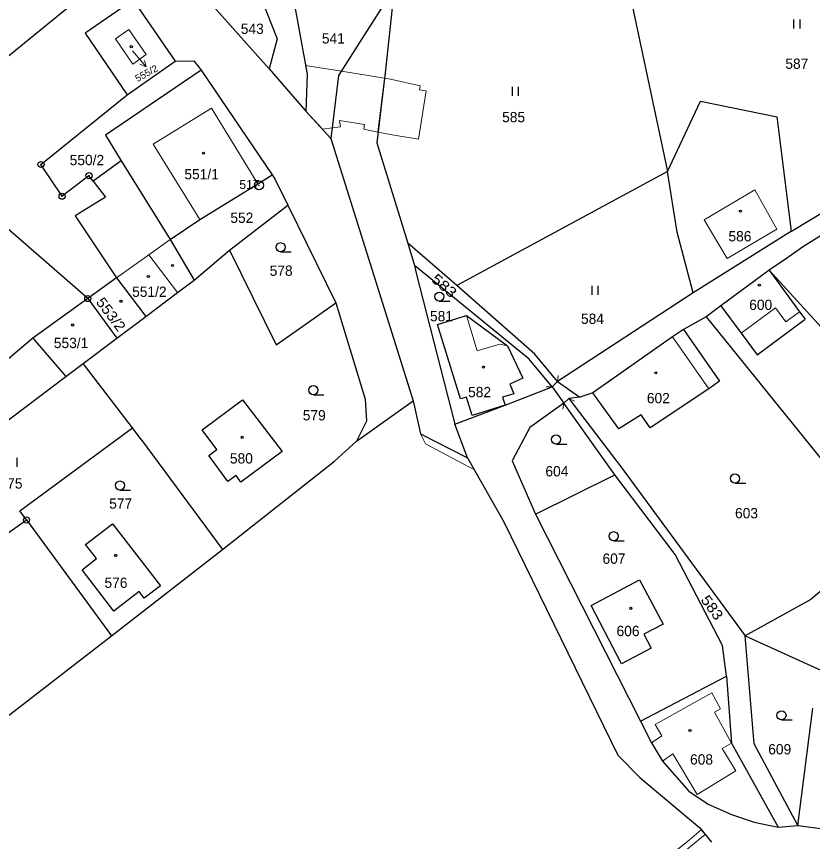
# Model space of a CAD drawing. Extents: x -727701 to -724405, y -960481 to -957284.
# Drawn here: x -726659.3 to -726527.9, y -958649.2 to -958512.9 of the extents above; entities that cross this region are included whole.
import ezdxf
from ezdxf.enums import TextEntityAlignment as Align

# ---------------------------------------------------------------- set-up
doc = ezdxf.new("R2010")
doc.units = 0
doc.header["$LTSCALE"] = 0.68
for name, color, linetype, lineweight in [('1', 7, 'Continuous', 25), ('13', 7, 'Continuous', 13), ('3', 7, 'Continuous', 25), ('4', 7, 'Continuous', 13), ('5', 7, 'Continuous', 25), ('7', 7, 'Continuous', 13), ('8', 7, 'Continuous', 25)]:
    doc.layers.add(name, color=color, linetype=linetype, lineweight=lineweight)
doc.layers.add('2', color=7, linetype='Continuous')

msp = doc.modelspace()

# ---------------------------------------------------------------- linework, layer by layer
at = {"layer": '1'}
for p, q in [((-726589.52, -958496.52), (-726606.15, -958522.69)), ((-726560.34, -958498.27), (-726551.81, -958538.56)), ((-726614.83, -958503.25), (-726611.35, -958522.45)), ((-726675.19, -958531.23), (-726642.56, -958504.67)), ((-726620.3, -958506.4), (-726616.3, -958516.65)), ((-726640.09, -958510.2), (-726648.01, -958515.68)), ((-726640.09, -958510.2), (-726633.12, -958520.3)), ((-726626.79, -958511.3), (-726617.62, -958521.61)), ((-726597.29, -958511.5), (-726598.38, -958521.76)), ((-726648.01, -958515.68), (-726641.04, -958525.85)), ((-726616.3, -958516.65), (-726617.62, -958521.61)), ((-726641.04, -958525.85), (-726633.12, -958520.3)), ((-726633.12, -958520.3), (-726630.04, -958520.28)), ((-726630.04, -958520.28), (-726628.82, -958521.8)), ((-726628.82, -958521.8), (-726644.64, -958532.56)), ((-726628.82, -958521.8), (-726617.11, -958539.11)), ((-726617.62, -958521.61), (-726611.55, -958528.6)), ((-726611.35, -958522.45), (-726611.55, -958528.6)), ((-726606.15, -958522.69), (-726607.4, -958533.1)), ((-726598.38, -958521.76), (-726599.84, -958533.79)), ((-726655.29, -958537.38), (-726641.04, -958525.85)), ((-726531.35, -958548.4), (-726493.92, -958525.75)), ((-726551.81, -958538.56), (-726546.39, -958526.95)), ((-726546.39, -958526.95), (-726533.73, -958529.52)), ((-726611.55, -958528.6), (-726607.4, -958533.1)), ((-726531.35, -958548.4), (-726533.73, -958529.52)), ((-726644.64, -958532.56), (-726642.02, -958536.77)), ((-726607.4, -958533.1), (-726593.8, -958576.44)), ((-726599.84, -958533.79), (-726594.7, -958550.4)), ((-726651.8, -958542.62), (-726655.29, -958537.38)), ((-726642.02, -958536.77), (-726646.68, -958540.14)), ((-726619.46, -958540.56), (-726617.11, -958539.11)), ((-726617.11, -958539.11), (-726616.6, -958539.86)), ((-726551.81, -958538.56), (-726586.59, -958557.34)), ((-726550.24, -958548.58), (-726551.81, -958538.56)), ((-726647.56, -958559.53), (-726669.8, -958540.17)), ((-726647.36, -958539.23), (-726651.8, -958542.62)), ((-726646.68, -958540.14), (-726647.36, -958539.23)), ((-726646.68, -958540.14), (-726644.66, -958542.77)), ((-726616.6, -958539.86), (-726614.53, -958544.08)), ((-726629.06, -958546.48), (-726619.46, -958540.56)), ((-726644.66, -958542.77), (-726649.67, -958545.84)), ((-726624.16, -958551.55), (-726614.53, -958544.08)), ((-726614.53, -958544.08), (-726606.58, -958560.24)), ((-726649.67, -958545.84), (-726642.79, -958556.11)), ((-726519.54, -958544.82), (-726529.33, -958550.91)), ((-726633.94, -958549.76), (-726629.06, -958546.48)), ((-726547.6, -958558.6), (-726550.24, -958548.58)), ((-726531.35, -958548.4), (-726547.6, -958558.6)), ((-726594.7, -958550.4), (-726593.6, -958554.05)), ((-726586.59, -958557.34), (-726594.7, -958550.4)), ((-726529.33, -958550.91), (-726532.32, -958553.04)), ((-726629.97, -958556.47), (-726624.16, -958551.55)), ((-726624.16, -958551.55), (-726616.43, -958567.15)), ((-726574.68, -958569.53), (-726593.6, -958554.05)), ((-726593.6, -958554.05), (-726593.3, -958555.32)), ((-726532.32, -958553.04), (-726535.05, -958554.83)), ((-726593.3, -958555.32), (-726586.95, -958580.24)), ((-726535.05, -958554.83), (-726543.01, -958560.7)), ((-726535.05, -958554.83), (-726529.99, -958561.69)), ((-726535.05, -958554.83), (-726513.21, -958578.81)), ((-726642.79, -958556.11), (-726647.56, -958559.53)), ((-726642.79, -958556.11), (-726637.97, -958562.48)), ((-726632.72, -958558.53), (-726629.97, -958556.47)), ((-726573.72, -958568.73), (-726586.59, -958557.34)), ((-726647.56, -958559.53), (-726656.62, -958566.04)), ((-726647.56, -958559.53), (-726642.74, -958566.06)), ((-726637.97, -958562.48), (-726632.72, -958558.53)), ((-726547.6, -958558.6), (-726569.98, -958573.22)), ((-726612.06, -958564.08), (-726606.58, -958560.24)), ((-726606.58, -958560.24), (-726601.76, -958576.16)), ((-726543.01, -958560.7), (-726545.42, -958562.55)), ((-726543.01, -958560.7), (-726539.67, -958565.22)), ((-726589.8, -958563.8), (-726585.04, -958562.33)), ((-726585.04, -958562.33), (-726578.22, -958567.32)), ((-726529.99, -958561.69), (-726529.06, -958562.95)), ((-726642.74, -958566.06), (-726637.97, -958562.48)), ((-726545.42, -958562.55), (-726549.2, -958564.62)), ((-726545.42, -958562.55), (-726525.15, -958587.59)), ((-726537.02, -958568.82), (-726529.06, -958562.95)), ((-726616.43, -958567.15), (-726612.06, -958564.08)), ((-726585.99, -958576.11), (-726589.8, -958563.8)), ((-726549.2, -958564.62), (-726550.99, -958565.87)), ((-726549.2, -958564.62), (-726543.21, -958573.17)), ((-726656.62, -958566.04), (-726663.23, -958571.63)), ((-726656.62, -958566.04), (-726651.21, -958572.42)), ((-726648.32, -958570.25), (-726642.74, -958566.06)), ((-726550.99, -958565.87), (-726564.15, -958575.09)), ((-726539.67, -958565.22), (-726537.02, -958568.82)), ((-726578.22, -958567.32), (-726575.7, -958572.69)), ((-726569.98, -958573.22), (-726573.72, -958568.73)), ((-726651.21, -958572.42), (-726648.32, -958570.25)), ((-726640.17, -958580.88), (-726648.32, -958570.25)), ((-726570.84, -958574.12), (-726574.68, -958569.53)), ((-726664.64, -958582.51), (-726651.21, -958572.42)), ((-726575.7, -958572.69), (-726577.87, -958573.66)), ((-726569.98, -958573.22), (-726566.3, -958575.8)), ((-726543.21, -958573.17), (-726544.99, -958574.42)), ((-726578.65, -958577.14), (-726570.84, -958574.12)), ((-726577.87, -958573.66), (-726577.22, -958575.24)), ((-726570.84, -958574.12), (-726568.93, -958576.81)), ((-726544.99, -958574.42), (-726554.7, -958580.85)), ((-726585.02, -958575.81), (-726585.99, -958576.11)), ((-726584.09, -958578.82), (-726585.02, -958575.81)), ((-726577.22, -958575.24), (-726579.06, -958575.81)), ((-726579.06, -958575.81), (-726578.65, -958577.14)), ((-726566.3, -958575.8), (-726568.09, -958576.04)), ((-726564.15, -958575.09), (-726566.3, -958575.8)), ((-726559.86, -958581.02), (-726564.15, -958575.09)), ((-726628.66, -958581.23), (-726622.01, -958576.27)), ((-726622.01, -958576.27), (-726615.48, -958584.8)), ((-726603.2, -958583.07), (-726593.8, -958576.44)), ((-726601.76, -958576.16), (-726601.52, -958579.77)), ((-726593.8, -958576.44), (-726592.62, -958581.84)), ((-726586.95, -958580.24), (-726578.65, -958577.14)), ((-726578.65, -958577.14), (-726584.09, -958578.82)), ((-726568.93, -958576.81), (-726574.54, -958580.82)), ((-726560.54, -958588.62), (-726568.93, -958576.81)), ((-726568.09, -958576.04), (-726559.3, -958587.61)), ((-726601.52, -958579.77), (-726603.2, -958583.07)), ((-726556.16, -958578.72), (-726559.86, -958581.02)), ((-726554.7, -958580.85), (-726556.16, -958578.72)), ((-726658.8, -958594.56), (-726640.17, -958580.88)), ((-726638.73, -958582.82), (-726640.17, -958580.88)), ((-726626.26, -958584.47), (-726628.66, -958581.23)), ((-726584.84, -958585.83), (-726586.95, -958580.24)), ((-726574.54, -958580.82), (-726577.49, -958586.32)), ((-726592.62, -958581.84), (-726584.84, -958585.83)), ((-726638.73, -958582.82), (-726625.3, -958600.97)), ((-726606.83, -958586.39), (-726603.2, -958583.07)), ((-726627.59, -958585.45), (-726626.26, -958584.47)), ((-726624.43, -958589.72), (-726627.59, -958585.45)), ((-726615.48, -958584.8), (-726622.27, -958589.83)), ((-726625.3, -958600.97), (-726606.83, -958586.39)), ((-726584.84, -958585.83), (-726578.83, -958596.41)), ((-726577.49, -958586.32), (-726573.61, -958595.11)), ((-726559.3, -958587.61), (-726538.98, -958615.21)), ((-726623.08, -958588.73), (-726624.43, -958589.72)), ((-726622.27, -958589.83), (-726623.08, -958588.73)), ((-726573.61, -958595.11), (-726560.54, -958588.62)), ((-726550.55, -958601.8), (-726560.54, -958588.62)), ((-726657.68, -958596.09), (-726658.8, -958594.56)), ((-726664.76, -958601.05), (-726657.68, -958596.09)), ((-726657.68, -958596.09), (-726643.63, -958615.25)), ((-726578.83, -958596.41), (-726560.04, -958634.92)), ((-726573.61, -958595.11), (-726556.27, -958629.31)), ((-726647.93, -958600.14), (-726643.49, -958596.7)), ((-726643.49, -958596.7), (-726635.56, -958606.94)), ((-726516.08, -958599.05), (-726528.15, -958609.2)), ((-726646.13, -958602.47), (-726647.93, -958600.14)), ((-726643.63, -958615.25), (-726625.3, -958600.97)), ((-726542.76, -958616.82), (-726550.55, -958601.8)), ((-726648.48, -958604.3), (-726646.13, -958602.47)), ((-726643.26, -958611.13), (-726648.48, -958604.3)), ((-726635.56, -958606.94), (-726638.25, -958609.02)), ((-726564.4, -958610.2), (-726556.42, -958605.99)), ((-726556.42, -958605.99), (-726552.55, -958613.3)), ((-726639.1, -958607.91), (-726643.26, -958611.13)), ((-726638.25, -958609.02), (-726639.1, -958607.91)), ((-726528.15, -958609.2), (-726538.98, -958615.21)), ((-726559.4, -958619.85), (-726564.4, -958610.2)), ((-726552.55, -958613.3), (-726555.74, -958614.95)), ((-726662.18, -958629.55), (-726643.63, -958615.25)), ((-726555.74, -958614.95), (-726554.49, -958617.24)), ((-726538.98, -958615.21), (-726509.08, -958628.88)), ((-726537.52, -958633.08), (-726538.98, -958615.21)), ((-726542.05, -958621.91), (-726542.76, -958616.82)), ((-726554.49, -958617.24), (-726559.4, -958619.85)), ((-726556.27, -958629.31), (-726542.05, -958621.91)), ((-726542.05, -958621.91), (-726541.22, -958632.97)), ((-726530.29, -958646.53), (-726527.8, -958627.19)), ((-726556.27, -958629.31), (-726554.47, -958632.9)), ((-726554.47, -958632.9), (-726552.65, -958635.94)), ((-726541.22, -958632.97), (-726533.53, -958646.81)), ((-726530.29, -958646.53), (-726537.52, -958633.08)), ((-726560.04, -958634.92), (-726556.38, -958638.6)), ((-726552.65, -958635.94), (-726548.32, -958640.9)), ((-726556.38, -958638.6), (-726546.5, -958646.95)), ((-726548.32, -958640.9), (-726545.1, -958643.02)), ((-726545.1, -958643.02), (-726541.23, -958644.71)), ((-726541.23, -958644.71), (-726537.51, -958645.99)), ((-726537.51, -958645.99), (-726533.53, -958646.81)), ((-726533.53, -958646.81), (-726530.29, -958646.53)), ((-726530.29, -958646.53), (-726526.5, -958647.05)), ((-726546.5, -958646.95), (-726544.57, -958649.29))]:
    msp.add_line(p, q, dxfattribs=at)
msp.add_lwpolyline([(-726642.02, -958536.77), (-726633.94, -958549.76), (-726629.97, -958556.47)], dxfattribs=at)
at = {"layer": '13'}
for points in [[(-726611.6, -958521.05), (-726611.35, -958522.45), (-726611.55, -958528.6), (-726608.81, -958531.57), (-726607.19, -958531.35), (-726606.15, -958522.69), (-726605.68, -958521.95)], [(-726605.68, -958521.95), (-726606.15, -958522.69), (-726607.19, -958531.35), (-726605.82, -958531.16), (-726605.97, -958530.1), (-726601.85, -958530.79), (-726601.97, -958531.55), (-726599.63, -958532.03), (-726598.55, -958523.15)], [(-726598.55, -958523.15), (-726599.63, -958532.03), (-726597.27, -958532.51), (-726592.95, -958533.2), (-726591.67, -958525.22), (-726592.79, -958525.04), (-726592.69, -958524.39), (-726597.58, -958523.31)], [(-726583.7, -958587.83), (-726584.84, -958585.83), (-726592.62, -958581.84), (-726591.8, -958583.54)], [(-726546.24, -958647.27), (-726548.21, -958648.89), (-726552.07, -958652.06), (-726551.47, -958652.57), (-726551.26, -958652.68), (-726550.37, -958651.95), (-726545.6, -958648.04)]]:
    msp.add_lwpolyline(points, close=True, dxfattribs=at)
at = {"layer": '3'}
for p, q in [((-726530.931, -958514.91), (-726530.931, -958513.41)), ((-726529.93, -958514.91), (-726529.93, -958513.41)), ((-726577.421, -958526.04), (-726577.421, -958524.54)), ((-726576.42, -958526.04), (-726576.42, -958524.54)), ((-726615.723, -958551.79), (-726613.973, -958551.79)), ((-726564.271, -958558.93), (-726564.271, -958557.43)), ((-726563.27, -958558.93), (-726563.27, -958557.43)), ((-726589.513, -958559.94), (-726587.763, -958559.94)), ((-726610.303, -958575.4), (-726608.553, -958575.4)), ((-726570.213, -958583.55), (-726568.463, -958583.55)), ((-726659.23, -958587.33), (-726659.23, -958585.83)), ((-726540.653, -958589.99), (-726538.903, -958589.99)), ((-726642.253, -958591.15), (-726640.503, -958591.15)), ((-726560.713, -958599.52), (-726558.963, -958599.52)), ((-726532.993, -958629.11), (-726531.243, -958629.11))]:
    msp.add_line(p, q, dxfattribs=at)
for centre in [(-726615.7229, -958551.0398), (-726589.5129, -958559.1898), (-726610.3029, -958574.6498), (-726570.2129, -958582.7998), (-726540.6529, -958589.2398), (-726642.2529, -958590.3998), (-726560.7129, -958598.7698), (-726532.9929, -958628.3598)]:
    msp.add_circle(centre, 0.75, dxfattribs=at)
at = {"layer": '4'}
for p, q in [((-726636.74, -958534.01), (-726627.14, -958528.1)), ((-726627.14, -958528.1), (-726619.46, -958540.56)), ((-726629.06, -958546.48), (-726636.74, -958534.01)), ((-726545.74, -958546.5), (-726537.4, -958541.55)), ((-726537.4, -958541.55), (-726533.76, -958548.07)), ((-726541.95, -958552.88), (-726545.74, -958546.5)), ((-726533.76, -958548.07), (-726541.95, -958552.88)), ((-726637.47, -958552.3), (-726633.94, -958549.76)), ((-726585.04, -958562.33), (-726583.23, -958568.17)), ((-726533.99, -958561.03), (-726539.67, -958565.22)), ((-726532.26, -958563.37), (-726533.99, -958561.03)), ((-726529.99, -958561.69), (-726532.26, -958563.37)), ((-726550.99, -958565.87), (-726544.99, -958574.42)), ((-726583.23, -958568.17), (-726579.52, -958567.03)), ((-726579.52, -958567.03), (-726578.22, -958567.32)), ((-726569.98, -958573.22), (-726570.84, -958574.12)), ((-726569.875, -958572.225), (-726569.979, -958573.219)), ((-726571.84, -958574.119), (-726570.841, -958574.119)), ((-726569.087, -958577.798), (-726568.931, -958576.81)), ((-726568.93, -958576.81), (-726568.09, -958576.04)), ((-726567.191, -958576.479), (-726568.09, -958576.041)), ((-726553.87, -958629.85), (-726544.52, -958624.64)), ((-726544.52, -958624.64), (-726543.06, -958627.26)), ((-726543.06, -958627.26), (-726544.08, -958627.82)), ((-726544.08, -958627.82), (-726541.22, -958632.97)), ((-726552.75, -958631.73), (-726553.87, -958629.85)), ((-726554.47, -958632.9), (-726552.75, -958631.73)), ((-726541.22, -958632.97), (-726542.8, -958633.84)), ((-726542.8, -958633.84), (-726540.51, -958637.52)), ((-726550.95, -958634.73), (-726552.65, -958635.94)), ((-726546.93, -958641.45), (-726550.95, -958634.73)), ((-726540.51, -958637.52), (-726546.93, -958641.45))]:
    msp.add_line(p, q, dxfattribs=at)
msp.add_lwpolyline([(-726643, -958516.65), (-726640.1, -958520.79), (-726637.91, -958519.22), (-726640.78, -958515.11)], close=True, dxfattribs=at)
msp.add_lwpolyline([(-726642.79, -958556.11), (-726637.47, -958552.3), (-726632.72, -958558.53)], dxfattribs=at)
at = {"layer": '5'}
for centre in [(-726640.3668, -958517.9192), (-726628.4568, -958535.5192), (-726539.7768, -958545.0792), (-726633.5768, -958554.0492), (-726637.5568, -958555.8892), (-726536.6568, -958557.2992), (-726642.0668, -958559.9692), (-726650.0668, -958563.8892), (-726582.1968, -958570.8392), (-726553.7368, -958571.7992), (-726622.0668, -958582.4392), (-726642.9468, -958601.9392), (-726557.8768, -958610.6892), (-726548.0968, -958630.8592)]:
    msp.add_circle(centre, 0.175, dxfattribs=at)
at = {"layer": '7'}
msp.add_line((-726637.941, -958521.269), (-726638.201, -958520.18), dxfattribs=at)
msp.add_lwpolyline([(-726640.16, -958518.62), (-726639.87, -958518.97), (-726637.941, -958521.269), (-726638.968, -958520.824)], dxfattribs=at)
at = {"layer": '8'}
for centre, radius in [((-726655.29, -958537.3799), 0.5), ((-726655.29, -958537.3799), 0.0303), ((-726647.36, -958539.2299), 0.5), ((-726647.36, -958539.2299), 0.0303), ((-726619.29, -958540.8298), 0.75), ((-726619.29, -958540.8298), 0.03), ((-726651.8, -958542.6199), 0.5), ((-726651.8, -958542.6199), 0.0303), ((-726647.56, -958559.5299), 0.5), ((-726647.56, -958559.5299), 0.0303), ((-726657.68, -958596.0899), 0.5), ((-726657.68, -958596.0899), 0.0303)]:
    msp.add_circle(centre, radius, dxfattribs=at)

# ---------------------------------------------------------------- texts
at = {"layer": '2'}
for s, p in [('543', (-726622.29, -958515.815)), ('541', (-726608.9, -958517.405)), ('587', (-726532.35, -958521.585)), ('585', (-726579.13, -958530.405)), ('552', (-726624.01, -958547.025)), ('586', (-726541.75, -958550.085)), ('578', (-726617.52, -958555.765)), ('600', (-726538.32, -958561.405)), ('581', (-726591.04, -958563.275)), ('584', (-726566.1, -958563.705)), ('582', (-726584.75, -958575.815)), ('602', (-726555.22, -958576.815)), ('579', (-726612.05, -958579.645)), ('580', (-726624.09, -958586.765)), ('604', (-726571.98, -958588.895)), ('575', (-726662.14, -958590.905)), ('603', (-726540.66, -958595.815)), ('607', (-726562.55, -958603.325)), ('576', (-726644.8, -958607.305)), ('606', (-726560.23, -958615.275)), ('609', (-726535.18, -958634.805)), ('608', (-726548.09, -958636.485))]:
    msp.add_text(s, height=1.7, dxfattribs=at).set_placement(p)
for s, height, rotation, width, p in [('555/2', 1.139, 29, 1.05, (-726637.6006, -958522.8209)), ('553/2', 1.7, 307, 1.1, (-726644.4129, -958562.6355))]:
    msp.add_text(s, height=height, rotation=rotation, dxfattribs=dict(at, width=width)).set_placement(p, align=Align.CENTER)
for s, p in [('550/2', (-726647.7, -958537.495)), ('551/1', (-726628.76, -958539.835)), ('551/2', (-726637.39, -958559.245)), ('553/1', (-726650.32, -958567.705)), ('577', (-726642.129, -958594.225))]:
    msp.add_text(s, height=1.7, dxfattribs=at).set_placement(p, align=Align.CENTER)
for rotation, width, p in [(319, 1.2, (-726590.958, -958556.55)), (306, 1.15, (-726546.413, -958609.289))]:
    msp.add_text('583', height=1.7, rotation=rotation, dxfattribs=dict(at, width=width)).set_placement(p)
at = {"layer": '8'}
msp.add_text('517', height=1.5, dxfattribs=at).set_placement((-726622.53, -958541.435))

doc.saveas('drawing.dxf')
